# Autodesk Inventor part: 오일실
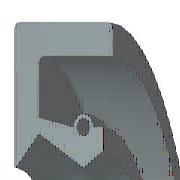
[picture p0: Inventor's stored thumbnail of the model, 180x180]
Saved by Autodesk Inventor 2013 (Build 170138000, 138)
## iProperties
IsCustomPart: 0
Company: 한국ATC센터
Created: 2014-10
Part Number: 오일실
Material: 고무
Description: 오일-실
Document SubType Name: Modeling
Standard: KS B 2804
Designer: KYOUNG IL JANG
Standards Organization: KS
Language: ko-KR
Size Designation: D - 17 32 8
Categories: <MemberInstance><Categories><Category DisplayName="샤프트 부품" InternalName="7f7aeb1f-a693-4053-b835-cee3144e0d98" Mnemonic="SHFT"><Category DisplayName="실링" Intern
Density: 0.93 g/cm^3
Mass: 2.28027 g
Surface Area: 32.1224 cm^2
Volume: 2.45191 cm^3
Author: KYOUNG IL JANG
Revision Number: 1
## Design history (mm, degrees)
revolve "본체" stored, may be unused: angle "d17" = 90 deg
revolve "스프링1" stored, may be unused: angle "d18" = 90 deg
body "Solid1"
sketch "스케치1"
  geometry: L1 (0, 16)-(8, 16); L2 (8, 14.25)-(1.75, 14.25); L3 (1.75, 10.25)-(4.9, 8.5); L4 (4.9, 8.5)-(0, 8.5); L5 (0, 0)-(9.586, 0) reference; L6 (4.9, 8.5)-(6.3, 9.375); L7 (0, 18)-(0, -3) reference; L8 (-1.941, 0)-(11.507, 0) reference; L9 (4.2, 10.6)-(1.75, 11.21); L10 (1.75, 11.21)-(1.75, 14.25); L11 (0, 16)-(0, 8.588); L12 (4.9, 8.5)-(0, 8.5); L13 (1.75, 10.25)-(0.152, 8.528); L14 (8, 16)-(8, 14.25); L15 (5.6, 10.6)-(6.3, 10.6); L16 (6.3, 10.6)-(6.3, 9.375); C1 r 0.455 at (4.9, 10.6); A1 r 0.7 centre (4.9, 10.6) between (5.6, 10.6) and (4.2, 10.6); A2 r 0.088 centre (0.088, 8.588) between (0, 8.588) and (0.152, 8.528); 1 further point
  constraints: 28 end point, 5 horizontal alignment, 5 point on line, 4 point on circle, 4 vertical alignment, 3 centre point, 3 tangent, 2 collinear, 2 horizontal, 2 perpendicular, 1 coincident, 1 parallel
  dimensions: "d0" = 32 diameter of L1 L5 (= SD2); "d1" = 1.75 distance of L1.end L2.start (= SD); "d2" = 0.91 diameter of C1 (= SPDI); "d3" = 1.4 diameter of A1 (= SPDA); "d4" = 17 diameter of L3.end L5 (= NND); "d5" = 20.5 diameter of L3.start L5 (= TKDM); "d7" = 22.42 diameter of L9.end L5 (= TKDM + 0.24 x SWDT); "d8" = 1.75 distance between parallel lines of L11 L10 (= SD); "d9" = 4.9 distance from line of L11 C1.centre (= SPDST); "d10" = 21.2 diameter of C1.centre L5 (= HLDM); "d11" = 0.0875 radius of A2 (= 0.25 x LAB); "d12" = 6.3 distance between parallel lines of L11 L16 (= SDI); "d13" = 18.75 diameter of L6.end L5 (= ABDM); "d14" = 8 distance from line of L11 L1.end (= SWDT)
fillet "모깎기1" dims "d6" = 0.3 (= RR)
other parameters: "SD2" = 32 [user parameter; used in 1 equation term], "SWDT" = 8 [user parameter; used in 2 equation terms], "RR" = 0.3 [user parameter; used in 1 equation term], "SD" = 1.75 [user parameter; used in 2 equation terms], "NND" = 17 [user parameter; used in 1 equation term], "SPDA" = 1.4 [user parameter; used in 1 equation term], "SPDI" = 0.91 [user parameter; used in 1 equation term], "TKDM" = 20.5 [user parameter; used in 2 equation terms], "HLDM" = 21.2 [user parameter; used in 1 equation term], "ABDM" = 18.75 [user parameter; used in 1 equation term], "SDI" = 6.3 [user parameter; used in 1 equation term], "SPDST" = 4.9 [user parameter; used in 1 equation term], "LAB" = 0.35 [user parameter; used in 1 equation term], "d15" = 0, "d16" = 0, "d19" = 0
